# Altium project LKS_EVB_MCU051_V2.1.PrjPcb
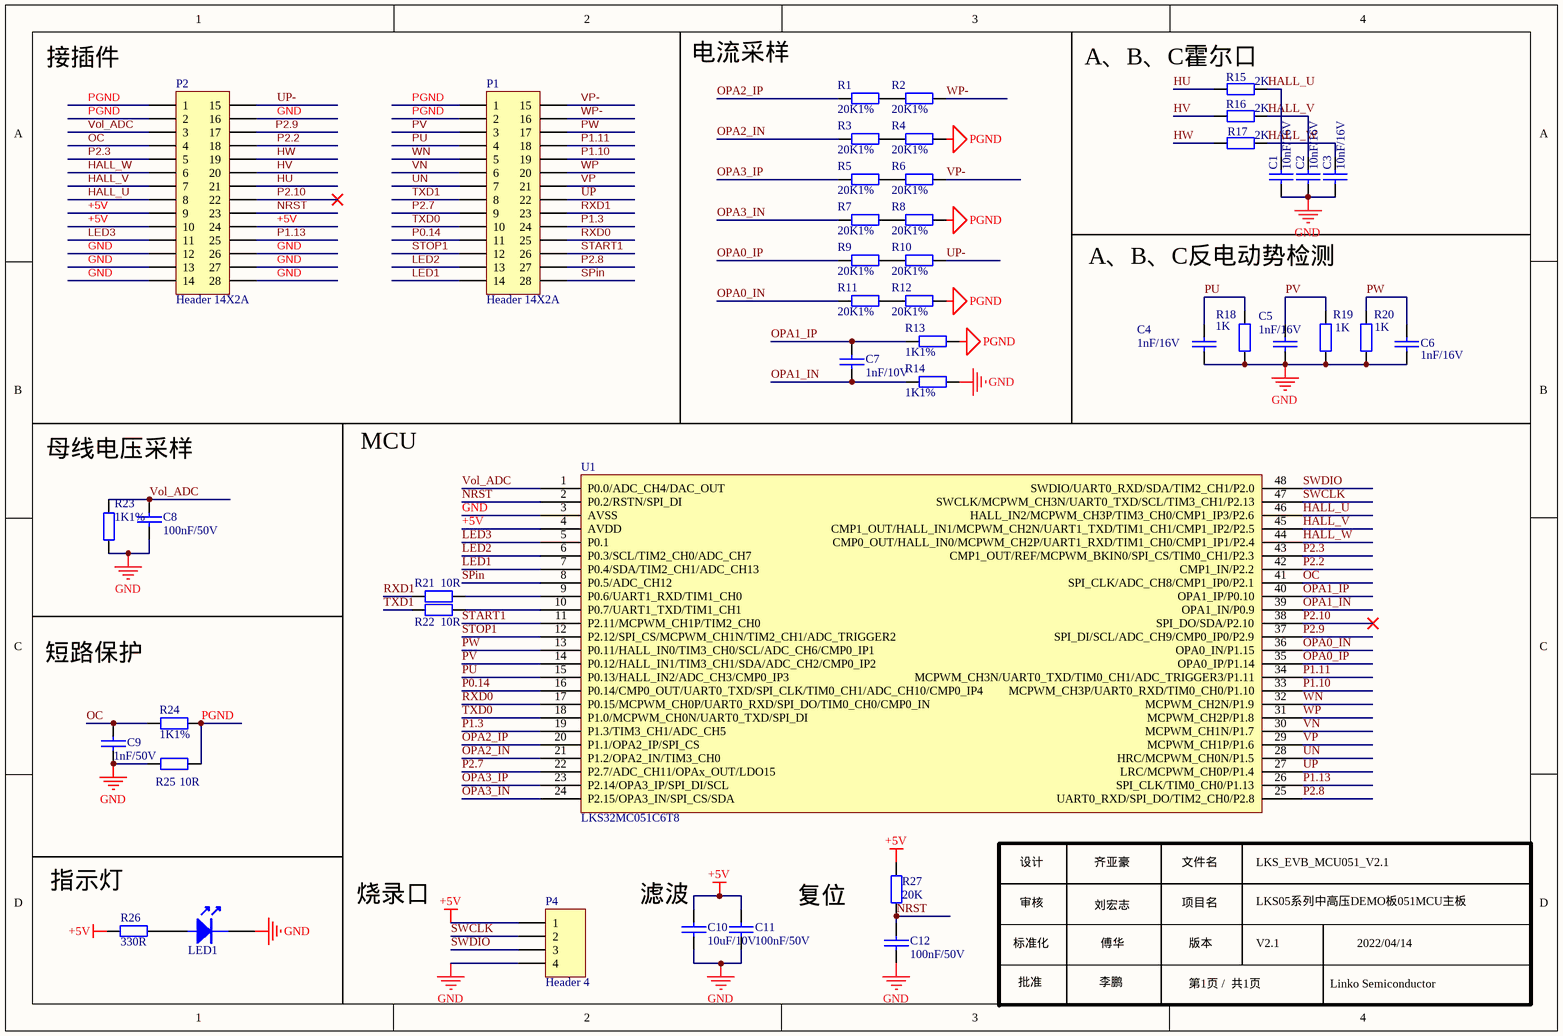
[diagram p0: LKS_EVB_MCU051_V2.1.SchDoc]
1 sheet, 44 parts. Net scope: global (net labels, ports and power ports of the same name join across sheets).
Board file: LKS_EVB_MCU051_V2.1.PcbDoc

## Sheet LKS_EVB_MCU051_V2.1.SchDoc
size A4; SheetNumber: 1; SheetTotal: 1

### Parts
C1  10nF/16V  [0603C]
C2  10nF/16V  [0603C]
C3  10nF/16V  [0603C]
C4  1nF/16V  [0603C]
C5  1nF/16V  [0603C]
C6  1nF/16V  [0603C]
C7  1nF/10V  [0603C]
C8  100nF/50V  [0603C]
C9  1nF/50V  [0603C]
C10  10uF/10V  [0603C]
C11  100nF/50V  [0603C]
C12  100nF/50V  [0603C]
LED1  LED  [LED 0603R]  (value not drawn)
P1  Header 14X2A  [HDR 2X14 顶层]
P2  Header 14X2A  [HDR 2X14 顶层]
P4  Header 4  [HDR1X4]
R1  20K1%  [0603R]
R2  20K1%  [0603R]
R3  20K1%  [0603R]
R4  20K1%  [0603R]
R5  20K1%  [0603R]
R6  20K1%  [0603R]
R7  20K1%  [0603R]
R8  20K1%  [0603R]
R9  20K1%  [0603R]
R10  20K1%  [0603R]
R11  20K1%  [0603R]
R12  20K1%  [0603R]
R13  1K1%  [0603R]
R14  1K1%  [0603R]
R15  2K  [0603R]
R16  2K  [0603R]
R17  2K  [0603R]
R18  1K  [0603R]
R19  1K  [0603R]
R20  1K  [0603R]
R21  10R  [0603R]
R22  10R  [0603R]
R23  1K1%  [0603R]
R24  1K1%  [0603R]
R25  10R  [0603R]
R26  330R  [0603R]
R27  20K  [0603R]
U1  LKS32MC051C6T8  [TQFP48]

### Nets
+5V: C10.2 C11.2 P2.9 P2.10 P2.24 P4.1 R26.1 R27.2 U1.4(AVDD)
GND: C1.2 C2.2 C3.2 C4.2 C5.2 C6.2 C8.1 C9.1 C10.1 C11.1 C12.2 LED1.2(K) P2.12 P2.13 P2.14 P2.16 P2.26 P2.27 P2.28 P4.4 R14.1 R18.2 R19.2 R20.2 R23.1 R25.2 U1.3(AVSS)
PGND: P1.1 P1.2 P2.1 P2.2 R4.1 R8.1 R12.1 R13.1 R24.2 R25.1
HALL_U: C1.1 P2.8 R15.2 U1.46(HALL_IN2/MCPWM_CH3P/TIM3_CH0/CMP1_IP3/P2.6)
HALL_V: C2.1 P2.7 R16.2 U1.45(CMP1_OUT/HALL_IN1/MCPWM_CH2N/UART1_TXD/TIM1_CH1/CMP1_IP2/P2.5)
HALL_W: C3.1 P2.6 R17.2 U1.44(CMP0_OUT/HALL_IN0/MCPWM_CH2P/UART1_RXD/TIM1_CH0/CMP1_IP1/P2.4)
HU: P2.21 R15.1
HV: P2.20 R16.1
HW: P2.19 R17.1
LED1: P1.14 U1.7(P0.4/SDA/TIM2_CH1/ADC_CH13)
LED2: P1.13 U1.6(P0.3/SCL/TIM2_CH0/ADC_CH7)
LED3: P2.11 U1.5(P0.1)
NRST: C12.1 P2.23 R27.1 U1.2(P0.2/RSTN/SPI_DI)
OC: C9.2 P2.4 R24.1 U1.41(SPI_CLK/ADC_CH8/CMP1_IP0/P2.1)
OPA0_IN: R11.2 U1.36(OPA0_IN/P1.15)
OPA0_IP: R9.2 U1.35(OPA0_IP/P1.14)
OPA1_IN: C7.2 R14.2 U1.39(OPA1_IN/P0.9)
OPA1_IP: C7.1 R13.2 U1.40(OPA1_IP/P0.10)
OPA2_IN: R3.2 U1.21(P1.2/OPA2_IN/TIM3_CH0)
OPA2_IP: R1.2 U1.20(P1.1/OPA2_IP/SPI_CS)
OPA3_IN: R7.2 U1.24(P2.15/OPA3_IN/SPI_CS/SDA)
OPA3_IP: R5.2 U1.23(P2.14/OPA3_IP/SPI_DI/SCL)
P0.14: P1.11 U1.16(P0.14/CMP0_OUT/UART0_TXD/SPI_CLK/TIM0_CH1/ADC_CH10/CMP0_IP4)
P1.3: P1.24 U1.19(P1.3/TIM3_CH1/ADC_CH5)
P1.10: P1.19 U1.33(MCPWM_CH3P/UART0_RXD/TIM0_CH0/P1.10)
P1.11: P1.18 U1.34(MCPWM_CH3N/UART0_TXD/TIM0_CH1/ADC_TRIGGER3/P1.11)
P1.13: P2.25 U1.26(SPI_CLK/TIM0_CH0/P1.13)
P2.2: P2.18 U1.42(CMP1_IN/P2.2)
P2.3: P2.5 U1.43(CMP1_OUT/REF/MCPWM_BKIN0/SPI_CS/TIM0_CH1/P2.3)
P2.7: P1.9 U1.22(P2.7/ADC_CH11/OPAx_OUT/LDO15)
P2.8: P1.27 U1.25(UART0_RXD/SPI_DO/TIM2_CH0/P2.8)
P2.9: P2.17 U1.37(SPI_DI/SCL/ADC_CH9/CMP0_IP0/P2.9)
P2.10: P2.22 U1.38(SPI_DO/SDA/P2.10)
PU: C4.1 P1.4 R18.1 U1.15(P0.13/HALL_IN2/ADC_CH3/CMP0_IP3)
PV: C5.1 P1.3 R19.1 U1.14(P0.12/HALL_IN1/TIM3_CH1/SDA/ADC_CH2/CMP0_IP2)
PW: C6.1 P1.17 R20.1 U1.13(P0.11/HALL_IN0/TIM3_CH0/SCL/ADC_CH6/CMP0_IP1)
RXD0: P1.25 U1.17(P0.15/MCPWM_CH0P/UART0_RXD/SPI_DO/TIM0_CH0/CMP0_IN)
RXD1: P1.23 R21.1
SPin: P1.28 U1.8(P0.5/ADC_CH12)
START1: P1.26 U1.11(P2.11/MCPWM_CH1P/TIM2_CH0)
STOP1: P1.12 U1.12(P2.12/SPI_CS/MCPWM_CH1N/TIM2_CH1/ADC_TRIGGER2)
SWCLK: P4.2 U1.47(SWCLK/MCPWM_CH3N/UART0_TXD/SCL/TIM3_CH1/P2.13)
SWDIO: P4.3 U1.48(SWDIO/UART0_RXD/SDA/TIM2_CH1/P2.0)
TXD0: P1.10 U1.18(P1.0/MCPWM_CH0N/UART0_TXD/SPI_DI)
TXD1: P1.8 R22.1
UN: P1.7 U1.28(HRC/MCPWM_CH0N/P1.5)
UP: P1.22 U1.27(LRC/MCPWM_CH0P/P1.4)
UP-: P2.15 R10.1
VN: P1.6 U1.30(MCPWM_CH1N/P1.7)
Vol_ADC: C8.2 P2.3 R23.2 U1.1(P0.0/ADC_CH4/DAC_OUT)
VP: P1.21 U1.29(MCPWM_CH1P/P1.6)
VP-: P1.15 R6.1
WN: P1.5 U1.32(MCPWM_CH2N/P1.9)
WP: P1.20 U1.31(MCPWM_CH2P/P1.8)
WP-: P1.16 R2.1
NetLED1_1: LED1.1(A) R26.2
NetR1_1: R1.1 R2.2
NetR3_1: R3.1 R4.2
NetR5_1: R5.1 R6.2
NetR7_1: R7.1 R8.2
NetR9_1: R9.1 R10.2
NetR11_1: R11.1 R12.2
NetR21_2: R21.2 U1.9(P0.6/UART1_RXD/TIM1_CH0)
NetR22_2: R22.2 U1.10(P0.7/UART1_TXD/TIM1_CH1)

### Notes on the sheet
- 接插件
- 电流采样
- A、B、C霍尔口
- A、B、C反电动势检测
- MCU
- 母线电压采样
- 短路保护
- (near R26) 指示灯
- 烧录口
- (near C10) 滤波
- 复位
- 设计
- 审核
- 齐亚豪
- 刘宏志
- 文件名
- 项目名
- LKS_EVB_MCU051_V2.1
- LKS05系列中高压DEMO板051MCU主板
- 标准化
- 批准
- 李鹏
- 傅华
- 版本
- 第1页 /  共1页
- V2.1
- Linko Semiconductor
- 2022/04/14

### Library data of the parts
C1-C6 = CAP: Capacitor
C7-C12 = C: Capacitor
LED1 = LED: LED_Light
P1 P2 = Header 14X2A: Header, 14-Pin, Dual row
P4 = Header 4: Header, 4-Pin
R1-R25 R27 = Res: Resistor; Value: K
R26 = Res: Resistor; Value: 330
U1 = LKS32MC051C6T8: 芯片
